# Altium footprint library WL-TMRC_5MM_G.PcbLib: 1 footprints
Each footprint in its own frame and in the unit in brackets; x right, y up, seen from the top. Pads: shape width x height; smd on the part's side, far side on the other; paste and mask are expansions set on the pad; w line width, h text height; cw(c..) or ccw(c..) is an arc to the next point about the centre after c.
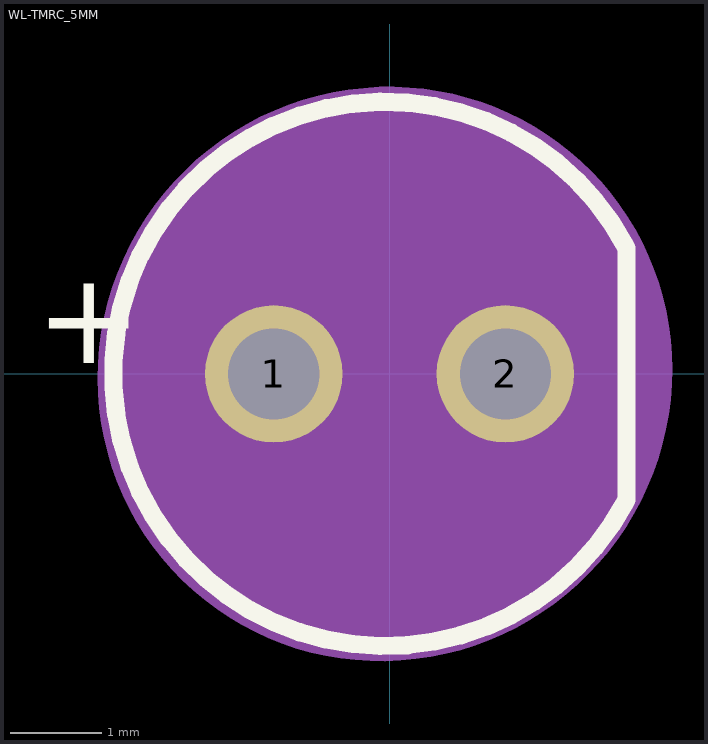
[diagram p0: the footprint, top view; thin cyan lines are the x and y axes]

## WL-TMRC_5MM [mm]
pads (2):
  round 1.508 hole 1: 1(-1.27,0) 2(1.27,0)
Top Overlay:
  lines w0.2: 2.589,-1.401 cw(c-0.047,0) 2.589,1.401 ; 2.6,-1.38 2.6,1.38
  text "+" at -3.88,0.118 h1.02
Assembly Top:
  circle w0.1: c0,0 r2.5
  lines w0.1: 2.493,-1.452 cw(c-0.021,0) 2.493,1.452 ; 2.5,-1.44 2.5,1.44
  text "+" at -3.887,0.131 h1.02
Courtyard Top:
  region: 0.216,3.141 0.376,3.126 0.534,3.103 0.692,3.071 0.847,3.031 1,2.983 1.151,2.928 1.298,2.865 1.442,2.794 1.582,2.715 1.718,2.63 1.849,2.538 1.975,2.439 2.096,2.334 2.212,2.222 2.321,2.105 2.424,1.982 2.521,1.854 2.611,1.721 2.694,1.584 2.77,1.443 2.838,1.297 2.899,1.149 2.952,0.998 2.997,0.844 3.034,0.688 3.063,0.53 3.083,0.371 3.096,0.211 3.1,0.05 3.096,-0.116 3.083,-0.281 3.061,-0.445 3.032,-0.608 2.993,-0.77 2.947,-0.929 2.892,-1.085 2.829,-1.238 2.759,-1.388 2.681,-1.534 2.595,-1.676 2.502,-1.813 2.402,-1.945 2.295,-2.072 2.182,-2.193 2.063,-2.308 1.938,-2.417 1.808,-2.519 1.672,-2.615 1.532,-2.703 1.387,-2.784 1.239,-2.857 1.087,-2.922 0.931,-2.98 0.773,-3.029 0.613,-3.07 0.45,-3.103 0.286,-3.127 0.121,-3.143 -0.049,-3.15 -0.052,-3.15 -0.211,-3.148 -0.374,-3.138 -0.537,-3.119 -0.699,-3.092 -0.859,-3.056 -1.017,-3.012 -1.173,-2.959 -1.325,-2.898 -1.474,-2.83 -1.619,-2.753 -1.76,-2.669 -1.896,-2.577 -2.027,-2.479 -2.153,-2.374 -2.273,-2.262 -2.387,-2.144 -2.495,-2.02 -2.595,-1.89 -2.689,-1.756 -2.776,-1.616 -2.855,-1.473 -2.926,-1.325 -2.99,-1.174 -3.045,-1.019 -3.092,-0.862 -3.131,-0.703 -3.161,-0.541 -3.183,-0.379 -3.196,-0.215 -3.2,-0.051 -3.196,0.118 -3.182,0.287 -3.16,0.455 -3.129,0.621 -3.089,0.786 -3.04,0.948 -2.983,1.108 -2.917,1.264 -2.844,1.416 -2.762,1.565 -2.673,1.709 -2.576,1.848 -2.472,1.981 -2.361,2.109 -2.243,2.231 -2.119,2.347 -1.989,2.455 -1.854,2.557 -1.713,2.652 -1.568,2.739 -1.418,2.818 -1.264,2.889 -1.107,2.951 -0.946,3.006 -0.783,3.051 -0.618,3.089 -0.451,3.117 -0.283,3.136 -0.114,3.147 0.051,3.148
